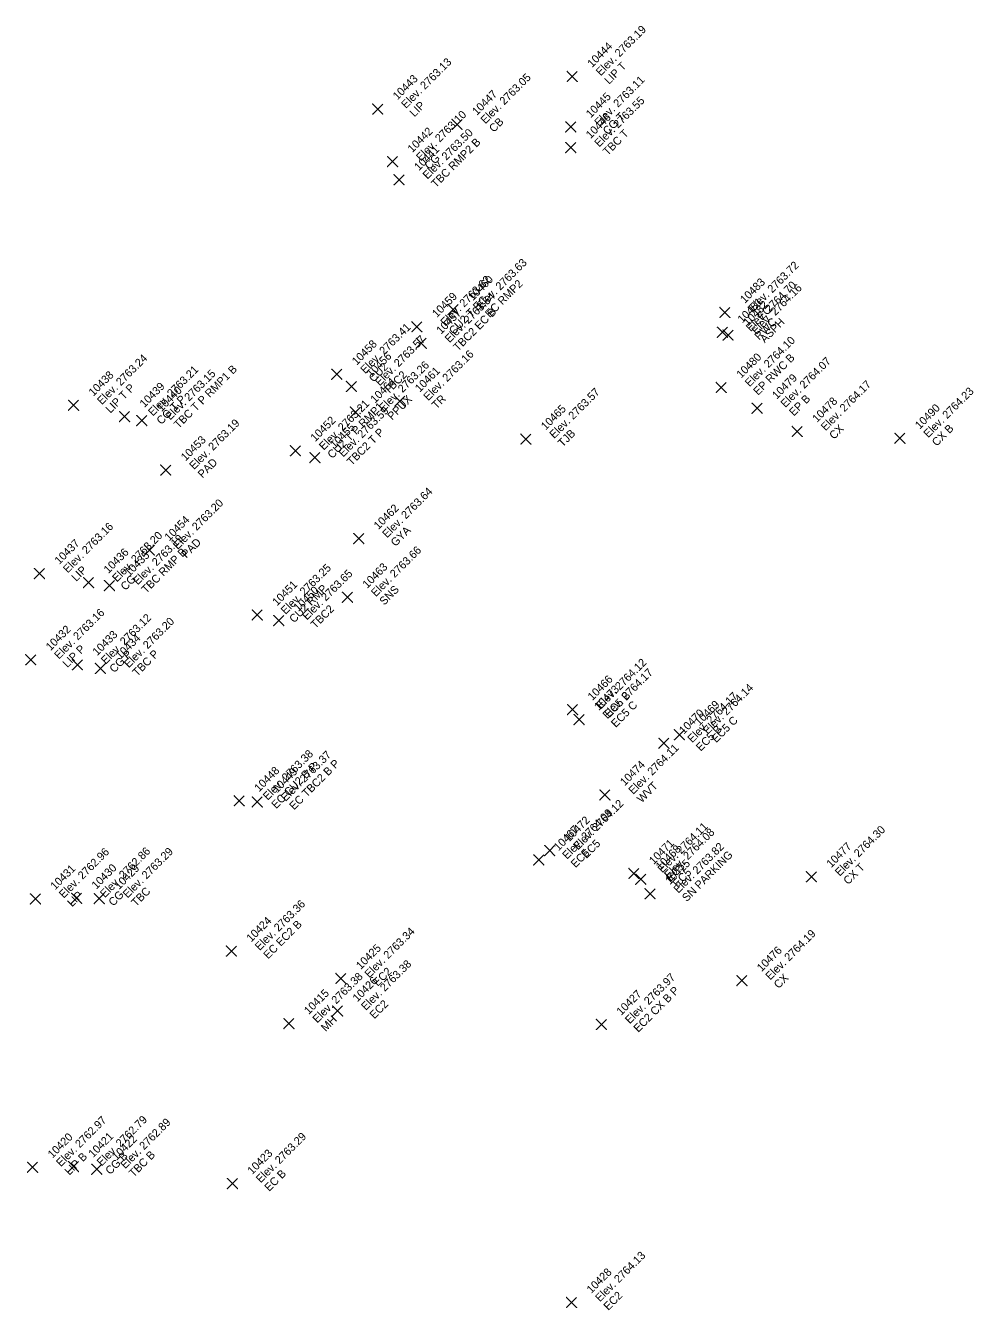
# Model space of a CAD drawing. Extents: x 2493999 to 2503109, y 700767 to 706646.
# Drawn here: x 2502616.97 to 2502645.41, y 701277.07 to 701315.61 of the extents above; entities that cross this region are included whole.
import ezdxf

# ---------------------------------------------------------------- set-up
doc = ezdxf.new("R2010")
doc.units = 0
doc.layers.add('ALG_CL_BLUE_Horiz', color=7, linetype='Continuous')
doc.layers.add('DES_SURFACE_Existing-Ground', color=7, linetype='Continuous')

msp = doc.modelspace()

# ---------------------------------------------------------------- linework, layer by layer
at = {"layer": 'ALG_CL_BLUE_Horiz'}
for points in [[(2502633.377, 701314.084), (2502633.227, 701314.234), (2502633.377, 701314.084), (2502633.227, 701313.934), (2502633.377, 701314.084), (2502633.527, 701313.934), (2502633.377, 701314.084), (2502633.527, 701314.234)], [(2502627.537, 701313.107), (2502627.387, 701313.257), (2502627.537, 701313.107), (2502627.387, 701312.957), (2502627.537, 701313.107), (2502627.687, 701312.957), (2502627.537, 701313.107), (2502627.687, 701313.257)], [(2502629.919, 701312.645), (2502629.769, 701312.795), (2502629.919, 701312.645), (2502629.769, 701312.495), (2502629.919, 701312.645), (2502630.069, 701312.495), (2502629.919, 701312.645), (2502630.069, 701312.795)], [(2502633.333, 701312.571), (2502633.183, 701312.721), (2502633.333, 701312.571), (2502633.183, 701312.421), (2502633.333, 701312.571), (2502633.483, 701312.421), (2502633.333, 701312.571), (2502633.483, 701312.721)], [(2502633.332, 701311.949), (2502633.182, 701312.099), (2502633.332, 701311.949), (2502633.182, 701311.799), (2502633.332, 701311.949), (2502633.482, 701311.799), (2502633.332, 701311.949), (2502633.482, 701312.099)], [(2502627.983, 701311.528), (2502627.833, 701311.678), (2502627.983, 701311.528), (2502627.833, 701311.378), (2502627.983, 701311.528), (2502628.133, 701311.378), (2502627.983, 701311.528), (2502628.133, 701311.678)], [(2502628.181, 701310.986), (2502628.031, 701311.136), (2502628.181, 701310.986), (2502628.031, 701310.836), (2502628.181, 701310.986), (2502628.331, 701310.836), (2502628.181, 701310.986), (2502628.331, 701311.136)], [(2502629.799, 701307.088), (2502629.649, 701307.238), (2502629.799, 701307.088), (2502629.649, 701306.938), (2502629.799, 701307.088), (2502629.949, 701306.938), (2502629.799, 701307.088), (2502629.949, 701307.238)], [(2502637.959, 701307.006), (2502637.809, 701307.156), (2502637.959, 701307.006), (2502637.809, 701306.856), (2502637.959, 701307.006), (2502638.109, 701306.856), (2502637.959, 701307.006), (2502638.109, 701307.156)], [(2502628.716, 701306.578), (2502628.566, 701306.728), (2502628.716, 701306.578), (2502628.566, 701306.428), (2502628.716, 701306.578), (2502628.866, 701306.428), (2502628.716, 701306.578), (2502628.866, 701306.728)], [(2502628.842, 701306.08), (2502628.692, 701306.23), (2502628.842, 701306.08), (2502628.692, 701305.93), (2502628.842, 701306.08), (2502628.992, 701305.93), (2502628.842, 701306.08), (2502628.992, 701306.23)], [(2502637.884, 701306.412), (2502637.734, 701306.562), (2502637.884, 701306.412), (2502637.734, 701306.262), (2502637.884, 701306.412), (2502638.034, 701306.262), (2502637.884, 701306.412), (2502638.034, 701306.562)], [(2502638.051, 701306.328), (2502637.901, 701306.478), (2502638.051, 701306.328), (2502637.901, 701306.178), (2502638.051, 701306.328), (2502638.201, 701306.178), (2502638.051, 701306.328), (2502638.201, 701306.478)], [(2502626.311, 701305.151), (2502626.161, 701305.301), (2502626.311, 701305.151), (2502626.161, 701305.001), (2502626.311, 701305.151), (2502626.461, 701305.001), (2502626.311, 701305.151), (2502626.461, 701305.301)], [(2502626.75, 701304.784), (2502626.6, 701304.934), (2502626.75, 701304.784), (2502626.6, 701304.634), (2502626.75, 701304.784), (2502626.9, 701304.634), (2502626.75, 701304.784), (2502626.9, 701304.934)], [(2502637.849, 701304.757), (2502637.699, 701304.907), (2502637.849, 701304.757), (2502637.699, 701304.607), (2502637.849, 701304.757), (2502637.999, 701304.607), (2502637.849, 701304.757), (2502637.999, 701304.907)], [(2502618.41, 701304.22), (2502618.26, 701304.37), (2502618.41, 701304.22), (2502618.26, 701304.07), (2502618.41, 701304.22), (2502618.56, 701304.07), (2502618.41, 701304.22), (2502618.56, 701304.37)], [(2502628.203, 701304.343), (2502628.053, 701304.493), (2502628.203, 701304.343), (2502628.053, 701304.193), (2502628.203, 701304.343), (2502628.353, 701304.193), (2502628.203, 701304.343), (2502628.353, 701304.493)], [(2502619.941, 701303.879), (2502619.791, 701304.029), (2502619.941, 701303.879), (2502619.791, 701303.729), (2502619.941, 701303.879), (2502620.091, 701303.729), (2502619.941, 701303.879), (2502620.091, 701304.029)], [(2502626.867, 701304.014), (2502626.717, 701304.164), (2502626.867, 701304.014), (2502626.717, 701303.864), (2502626.867, 701304.014), (2502627.017, 701303.864), (2502626.867, 701304.014), (2502627.017, 701304.164)], [(2502638.921, 701304.133), (2502638.771, 701304.283), (2502638.921, 701304.133), (2502638.771, 701303.983), (2502638.921, 701304.133), (2502639.071, 701303.983), (2502638.921, 701304.133), (2502639.071, 701304.283)], [(2502620.459, 701303.76), (2502620.309, 701303.91), (2502620.459, 701303.76), (2502620.309, 701303.61), (2502620.459, 701303.76), (2502620.609, 701303.61), (2502620.459, 701303.76), (2502620.609, 701303.91)], [(2502640.128, 701303.435), (2502639.978, 701303.585), (2502640.128, 701303.435), (2502639.978, 701303.285), (2502640.128, 701303.435), (2502640.278, 701303.285), (2502640.128, 701303.435), (2502640.278, 701303.585)], [(2502631.985, 701303.205), (2502631.835, 701303.355), (2502631.985, 701303.205), (2502631.835, 701303.055), (2502631.985, 701303.205), (2502632.135, 701303.055), (2502631.985, 701303.205), (2502632.135, 701303.355)], [(2502643.208, 701303.23), (2502643.058, 701303.38), (2502643.208, 701303.23), (2502643.058, 701303.08), (2502643.208, 701303.23), (2502643.358, 701303.08), (2502643.208, 701303.23), (2502643.358, 701303.38)], [(2502625.069, 701302.858), (2502624.919, 701303.008), (2502625.069, 701302.858), (2502624.919, 701302.708), (2502625.069, 701302.858), (2502625.219, 701302.708), (2502625.069, 701302.858), (2502625.219, 701303.008)], [(2502625.653, 701302.65), (2502625.503, 701302.8), (2502625.653, 701302.65), (2502625.503, 701302.5), (2502625.653, 701302.65), (2502625.803, 701302.5), (2502625.653, 701302.65), (2502625.803, 701302.8)], [(2502621.179, 701302.275), (2502621.029, 701302.425), (2502621.179, 701302.275), (2502621.029, 701302.125), (2502621.179, 701302.275), (2502621.329, 701302.125), (2502621.179, 701302.275), (2502621.329, 701302.425)], [(2502626.967, 701300.223), (2502626.817, 701300.373), (2502626.967, 701300.223), (2502626.817, 701300.073), (2502626.967, 701300.223), (2502627.117, 701300.073), (2502626.967, 701300.223), (2502627.117, 701300.373)], [(2502620.689, 701299.877), (2502620.539, 701300.027), (2502620.689, 701299.877), (2502620.539, 701299.727), (2502620.689, 701299.877), (2502620.839, 701299.727), (2502620.689, 701299.877), (2502620.839, 701300.027)], [(2502617.388, 701299.172), (2502617.238, 701299.322), (2502617.388, 701299.172), (2502617.238, 701299.022), (2502617.388, 701299.172), (2502617.538, 701299.022), (2502617.388, 701299.172), (2502617.538, 701299.322)], [(2502618.862, 701298.903), (2502618.712, 701299.053), (2502618.862, 701298.903), (2502618.712, 701298.753), (2502618.862, 701298.903), (2502619.012, 701298.753), (2502618.862, 701298.903), (2502619.012, 701299.053)], [(2502619.487, 701298.813), (2502619.337, 701298.963), (2502619.487, 701298.813), (2502619.337, 701298.663), (2502619.487, 701298.813), (2502619.637, 701298.663), (2502619.487, 701298.813), (2502619.637, 701298.963)], [(2502626.63, 701298.461), (2502626.48, 701298.611), (2502626.63, 701298.461), (2502626.48, 701298.311), (2502626.63, 701298.461), (2502626.78, 701298.311), (2502626.63, 701298.461), (2502626.78, 701298.611)], [(2502623.923, 701297.931), (2502623.773, 701298.081), (2502623.923, 701297.931), (2502623.773, 701297.781), (2502623.923, 701297.931), (2502624.073, 701297.781), (2502623.923, 701297.931), (2502624.073, 701298.081)], [(2502624.566, 701297.761), (2502624.416, 701297.911), (2502624.566, 701297.761), (2502624.416, 701297.611), (2502624.566, 701297.761), (2502624.716, 701297.611), (2502624.566, 701297.761), (2502624.716, 701297.911)], [(2502617.124, 701296.588), (2502616.974, 701296.738), (2502617.124, 701296.588), (2502616.974, 701296.438), (2502617.124, 701296.588), (2502617.274, 701296.438), (2502617.124, 701296.588), (2502617.274, 701296.738)], [(2502618.527, 701296.434), (2502618.377, 701296.584), (2502618.527, 701296.434), (2502618.377, 701296.284), (2502618.527, 701296.434), (2502618.677, 701296.284), (2502618.527, 701296.434), (2502618.677, 701296.584)], [(2502619.218, 701296.327), (2502619.068, 701296.477), (2502619.218, 701296.327), (2502619.068, 701296.177), (2502619.218, 701296.327), (2502619.368, 701296.177), (2502619.218, 701296.327), (2502619.368, 701296.477)], [(2502633.386, 701295.093), (2502633.236, 701295.243), (2502633.386, 701295.093), (2502633.236, 701294.943), (2502633.386, 701295.093), (2502633.536, 701294.943), (2502633.386, 701295.093), (2502633.536, 701295.243)], [(2502633.579, 701294.793), (2502633.429, 701294.943), (2502633.579, 701294.793), (2502633.429, 701294.643), (2502633.579, 701294.793), (2502633.729, 701294.643), (2502633.579, 701294.793), (2502633.729, 701294.943)], [(2502636.594, 701294.335), (2502636.444, 701294.485), (2502636.594, 701294.335), (2502636.444, 701294.185), (2502636.594, 701294.335), (2502636.744, 701294.185), (2502636.594, 701294.335), (2502636.744, 701294.485)], [(2502636.128, 701294.079), (2502635.978, 701294.229), (2502636.128, 701294.079), (2502635.978, 701293.929), (2502636.128, 701294.079), (2502636.278, 701293.929), (2502636.128, 701294.079), (2502636.278, 701294.229)], [(2502623.385, 701292.355), (2502623.235, 701292.505), (2502623.385, 701292.355), (2502623.235, 701292.205), (2502623.385, 701292.355), (2502623.535, 701292.205), (2502623.385, 701292.355), (2502623.535, 701292.505)], [(2502623.925, 701292.32), (2502623.775, 701292.47), (2502623.925, 701292.32), (2502623.775, 701292.17), (2502623.925, 701292.32), (2502624.075, 701292.17), (2502623.925, 701292.32), (2502624.075, 701292.47)], [(2502634.357, 701292.531), (2502634.207, 701292.681), (2502634.357, 701292.531), (2502634.207, 701292.381), (2502634.357, 701292.531), (2502634.507, 701292.381), (2502634.357, 701292.531), (2502634.507, 701292.681)], [(2502632.698, 701290.863), (2502632.548, 701291.013), (2502632.698, 701290.863), (2502632.548, 701290.713), (2502632.698, 701290.863), (2502632.848, 701290.713), (2502632.698, 701290.863), (2502632.848, 701291.013)], [(2502632.37, 701290.583), (2502632.22, 701290.733), (2502632.37, 701290.583), (2502632.22, 701290.433), (2502632.37, 701290.583), (2502632.52, 701290.433), (2502632.37, 701290.583), (2502632.52, 701290.733)], [(2502635.228, 701290.175), (2502635.078, 701290.325), (2502635.228, 701290.175), (2502635.078, 701290.025), (2502635.228, 701290.175), (2502635.378, 701290.025), (2502635.228, 701290.175), (2502635.378, 701290.325)], [(2502635.43, 701290), (2502635.28, 701290.15), (2502635.43, 701290), (2502635.28, 701289.85), (2502635.43, 701290), (2502635.58, 701289.85), (2502635.43, 701290), (2502635.58, 701290.15)], [(2502640.552, 701290.078), (2502640.402, 701290.228), (2502640.552, 701290.078), (2502640.402, 701289.928), (2502640.552, 701290.078), (2502640.702, 701289.928), (2502640.552, 701290.078), (2502640.702, 701290.228)], [(2502635.71, 701289.568), (2502635.56, 701289.718), (2502635.71, 701289.568), (2502635.56, 701289.418), (2502635.71, 701289.568), (2502635.86, 701289.418), (2502635.71, 701289.568), (2502635.86, 701289.718)], [(2502617.265, 701289.412), (2502617.115, 701289.562), (2502617.265, 701289.412), (2502617.115, 701289.262), (2502617.265, 701289.412), (2502617.415, 701289.262), (2502617.265, 701289.412), (2502617.415, 701289.562)], [(2502618.499, 701289.433), (2502618.349, 701289.583), (2502618.499, 701289.433), (2502618.349, 701289.283), (2502618.499, 701289.433), (2502618.649, 701289.283), (2502618.499, 701289.433), (2502618.649, 701289.583)], [(2502619.182, 701289.422), (2502619.032, 701289.572), (2502619.182, 701289.422), (2502619.032, 701289.272), (2502619.182, 701289.422), (2502619.332, 701289.272), (2502619.182, 701289.422), (2502619.332, 701289.572)], [(2502623.147, 701287.849), (2502622.997, 701287.999), (2502623.147, 701287.849), (2502622.997, 701287.699), (2502623.147, 701287.849), (2502623.297, 701287.699), (2502623.147, 701287.849), (2502623.297, 701287.999)], [(2502626.435, 701287.027), (2502626.285, 701287.177), (2502626.435, 701287.027), (2502626.285, 701286.877), (2502626.435, 701287.027), (2502626.585, 701286.877), (2502626.435, 701287.027), (2502626.585, 701287.177)], [(2502638.465, 701286.96), (2502638.315, 701287.11), (2502638.465, 701286.96), (2502638.315, 701286.81), (2502638.465, 701286.96), (2502638.615, 701286.81), (2502638.465, 701286.96), (2502638.615, 701287.11)], [(2502626.333, 701286.05), (2502626.183, 701286.2), (2502626.333, 701286.05), (2502626.183, 701285.9), (2502626.333, 701286.05), (2502626.483, 701285.9), (2502626.333, 701286.05), (2502626.483, 701286.2)], [(2502624.875, 701285.674), (2502624.725, 701285.824), (2502624.875, 701285.674), (2502624.725, 701285.524), (2502624.875, 701285.674), (2502625.025, 701285.524), (2502624.875, 701285.674), (2502625.025, 701285.824)], [(2502634.252, 701285.649), (2502634.102, 701285.799), (2502634.252, 701285.649), (2502634.102, 701285.499), (2502634.252, 701285.649), (2502634.402, 701285.499), (2502634.252, 701285.649), (2502634.402, 701285.799)], [(2502617.183, 701281.361), (2502617.033, 701281.511), (2502617.183, 701281.361), (2502617.033, 701281.211), (2502617.183, 701281.361), (2502617.333, 701281.211), (2502617.183, 701281.361), (2502617.333, 701281.511)], [(2502618.404, 701281.38), (2502618.254, 701281.53), (2502618.404, 701281.38), (2502618.254, 701281.23), (2502618.404, 701281.38), (2502618.554, 701281.23), (2502618.404, 701281.38), (2502618.554, 701281.53)], [(2502619.109, 701281.301), (2502618.959, 701281.451), (2502619.109, 701281.301), (2502618.959, 701281.151), (2502619.109, 701281.301), (2502619.259, 701281.151), (2502619.109, 701281.301), (2502619.259, 701281.451)], [(2502623.178, 701280.874), (2502623.028, 701281.024), (2502623.178, 701280.874), (2502623.028, 701280.724), (2502623.178, 701280.874), (2502623.328, 701280.724), (2502623.178, 701280.874), (2502623.328, 701281.024)], [(2502633.356, 701277.307), (2502633.206, 701277.457), (2502633.356, 701277.307), (2502633.206, 701277.157), (2502633.356, 701277.307), (2502633.506, 701277.157), (2502633.356, 701277.307), (2502633.506, 701277.457)]]:
    msp.add_lwpolyline(points, dxfattribs=at)

# ---------------------------------------------------------------- texts
at = {"layer": 'DES_SURFACE_Existing-Ground'}
for s, p in [('Elev. 2763.19', (2502634.226, 701314.084)), ('10444', (2502633.971, 701314.339)), ('Elev. 2763.13', (2502628.386, 701313.107)), ('LIP T', (2502634.48, 701313.829)), ('10443', (2502628.131, 701313.362)), ('Elev. 2763.05', (2502630.768, 701312.645)), ('Elev. 2763.11', (2502634.182, 701312.571)), ('10447', (2502630.513, 701312.9)), ('10445', (2502633.927, 701312.826)), ('LIP', (2502628.64, 701312.852)), ('Elev. 2763.55', (2502634.181, 701311.949)), ('Elev. 2763.10', (2502628.832, 701311.528)), ('CB', (2502631.022, 701312.39)), ('10446', (2502633.926, 701312.204)), ('CG T', (2502634.436, 701312.316)), ('10442', (2502628.577, 701311.783)), ('Elev. 2763.50', (2502629.03, 701310.986)), ('TBC T', (2502634.435, 701311.694)), ('TBC RMP2 B', (2502629.284, 701310.731)), ('10441', (2502628.775, 701311.241)), ('CG', (2502629.086, 701311.273)), ('Elev. 2763.63', (2502630.648, 701307.088)), ('Elev. 2763.72', (2502638.808, 701307.006)), ('Elev. 2763.62', (2502629.565, 701306.578)), ('10460', (2502630.393, 701307.343)), ('EC RMP2', (2502630.902, 701306.833)), ('10483', (2502638.553, 701307.261)), ('Elev. 2764.70', (2502638.733, 701306.412)), ('Elev. 2764.16', (2502638.9, 701306.328)), ('10459', (2502629.31, 701306.833)), ('Elev. 2763.54', (2502629.691, 701306.08)), ('CU2 T EC', (2502629.819, 701306.323)), ('10481', (2502638.478, 701306.667)), ('10457', (2502629.436, 701306.335)), ('TBC2 EC B', (2502629.945, 701305.825)), ('10482', (2502638.645, 701306.583)), ('EC', (2502639.062, 701306.751)), ('Elev. 2763.41', (2502627.16, 701305.151)), ('RWC', (2502638.987, 701306.157)), ('ASPH', (2502639.154, 701306.073)), ('Elev. 2763.57', (2502627.599, 701304.784)), ('Elev. 2764.10', (2502638.698, 701304.757)), ('10458', (2502626.905, 701305.406)), ('Elev. 2763.16', (2502629.052, 701304.343)), ('Elev. 2763.24', (2502619.259, 701304.22)), ('10456', (2502627.344, 701305.039)), ('CU2', (2502627.414, 701304.896)), ('Elev. 2763.26', (2502627.716, 701304.014)), ('10480', (2502638.443, 701305.012)), ('EP RWC B', (2502638.952, 701304.502)), ('Elev. 2764.07', (2502639.77, 701304.133)), ('10438', (2502619.004, 701304.475)), ('Elev. 2763.21', (2502620.79, 701303.879)), ('Elev. 2763.15', (2502621.308, 701303.76)), ('TBC T P RMP1 B', (2502621.562, 701303.505)), ('TBC2', (2502627.853, 701304.529)), ('10461', (2502628.797, 701304.598)), ('10479', (2502639.515, 701304.388)), ('LIP T P', (2502619.513, 701303.965)), ('10439', (2502620.535, 701304.134)), ('10440', (2502621.053, 701304.015)), ('10464', (2502627.461, 701304.269)), ('Elev. 2763.57', (2502632.834, 701303.205)), ('Elev. 2764.17', (2502640.977, 701303.435)), ('Elev. 2764.23', (2502644.057, 701303.23)), ('CG T P', (2502621.044, 701303.624)), ('Elev. 2763.21', (2502625.918, 701302.858)), ('PPUX', (2502627.97, 701303.759)), ('TR', (2502629.306, 701304.088)), ('EP B', (2502640.024, 701303.878)), ('10478', (2502640.722, 701303.69)), ('CU2 T P RMP1', (2502626.172, 701302.603)), ('Elev. 2763.59', (2502626.502, 701302.65)), ('10465', (2502632.579, 701303.46)), ('10490', (2502643.802, 701303.485)), ('Elev. 2763.19', (2502622.028, 701302.275)), ('10452', (2502625.663, 701303.113)), ('10455', (2502626.247, 701302.905)), ('CX', (2502641.231, 701303.18)), ('CX B', (2502644.311, 701302.975)), ('10453', (2502621.773, 701302.53)), ('TBC2 T P', (2502626.756, 701302.395)), ('TJB', (2502633.088, 701302.95)), ('PAD', (2502622.282, 701302.02)), ('Elev. 2763.64', (2502627.816, 701300.223)), ('Elev. 2763.20', (2502621.538, 701299.877)), ('10462', (2502627.561, 701300.478)), ('10454', (2502621.283, 701300.132)), ('Elev. 2763.16', (2502618.237, 701299.172)), ('GYA', (2502628.07, 701299.968)), ('10437', (2502617.982, 701299.427)), ('Elev. 2763.20', (2502619.711, 701298.903)), ('Elev. 2763.19', (2502620.336, 701298.813)), ('PAD', (2502621.792, 701299.622)), ('10436', (2502619.456, 701299.158)), ('10435', (2502620.081, 701299.068)), ('TBC RMP B', (2502620.59, 701298.558)), ('Elev. 2763.66', (2502627.479, 701298.461)), ('LIP', (2502618.491, 701298.917)), ('Elev. 2763.25', (2502624.772, 701297.931)), ('Elev. 2763.65', (2502625.415, 701297.761)), ('10463', (2502627.224, 701298.716)), ('CG', (2502619.965, 701298.648)), ('10451', (2502624.517, 701298.186)), ('CU2 RMP', (2502625.026, 701297.676)), ('10450', (2502625.16, 701298.016)), ('SNS', (2502627.733, 701298.206)), ('TBC2', (2502625.669, 701297.506)), ('Elev. 2763.16', (2502617.973, 701296.588)), ('Elev. 2763.12', (2502619.376, 701296.434)), ('Elev. 2763.20', (2502620.067, 701296.327)), ('10432', (2502617.718, 701296.843)), ('10433', (2502619.121, 701296.689)), ('LIP P', (2502618.227, 701296.333)), ('10434', (2502619.812, 701296.582)), ('CG P', (2502619.63, 701296.179)), ('TBC P', (2502620.321, 701296.072)), ('Elev. 2764.12', (2502634.235, 701295.093)), ('Elev. 2764.17', (2502634.428, 701294.793)), ('10466', (2502633.98, 701295.348)), ('Elev. 2764.14', (2502637.443, 701294.335)), ('10473', (2502634.173, 701295.048)), ('EC5 B', (2502634.489, 701294.838)), ('Elev. 2764.17', (2502636.977, 701294.079)), ('EC5 C', (2502634.682, 701294.538)), ('10470', (2502636.722, 701294.334)), ('10469', (2502637.188, 701294.59)), ('EC5 C', (2502637.697, 701294.08)), ('EC5 B', (2502637.231, 701293.824)), ('Elev. 2764.11', (2502635.206, 701292.531)), ('Elev. 2763.38', (2502624.234, 701292.355)), ('Elev. 2763.37', (2502624.774, 701292.32)), ('EC TBC2 B P', (2502625.028, 701292.065)), ('10474', (2502634.951, 701292.786)), ('10448', (2502623.979, 701292.61)), ('EC CU2 B P', (2502624.488, 701292.1)), ('10449', (2502624.519, 701292.575)), ('WVT', (2502635.46, 701292.276)), ('Elev. 2764.12', (2502633.547, 701290.863)), ('Elev. 2764.09', (2502633.219, 701290.583)), ('10467', (2502632.964, 701290.838)), ('10472', (2502633.292, 701291.118)), ('Elev. 2764.11', (2502636.077, 701290.175)), ('Elev. 2764.30', (2502641.401, 701290.078)), ('EC5', (2502633.801, 701290.608)), ('Elev. 2764.08', (2502636.279, 701290)), ('Elev. 2762.96', (2502618.114, 701289.412)), ('Elev. 2762.86', (2502619.348, 701289.433)), ('Elev. 2763.29', (2502620.031, 701289.422)), ('EC5', (2502633.473, 701290.328)), ('10471', (2502635.822, 701290.43)), ('10468', (2502636.024, 701290.255)), ('Elev. 2763.82', (2502636.559, 701289.568)), ('SN PARKING', (2502636.813, 701289.313)), ('10477', (2502641.146, 701290.333)), ('10430', (2502619.093, 701289.688)), ('10429', (2502619.776, 701289.677)), ('EC5', (2502636.331, 701289.92)), ('10475', (2502636.304, 701289.823)), ('CX T', (2502641.655, 701289.823)), ('10431', (2502617.859, 701289.667)), ('EC5', (2502636.533, 701289.745)), ('TBC', (2502620.285, 701289.167)), ('LIP', (2502618.368, 701289.157)), ('CG', (2502619.602, 701289.178)), ('Elev. 2763.36', (2502623.996, 701287.849)), ('10424', (2502623.741, 701288.104)), ('EC EC2 B', (2502624.25, 701287.594)), ('Elev. 2763.34', (2502627.284, 701287.027)), ('Elev. 2764.19', (2502639.314, 701286.96)), ('10425', (2502627.029, 701287.282)), ('10476', (2502639.059, 701287.215)), ('Elev. 2763.38', (2502627.182, 701286.05)), ('EC2', (2502627.538, 701286.772)), ('Elev. 2763.38', (2502625.724, 701285.674)), ('10426', (2502626.927, 701286.305)), ('Elev. 2763.97', (2502635.101, 701285.649)), ('CX', (2502639.568, 701286.705)), ('10415', (2502625.469, 701285.929)), ('10427', (2502634.846, 701285.904)), ('EC2 CX B P', (2502635.355, 701285.394)), ('EC2', (2502627.436, 701285.795)), ('MH', (2502625.978, 701285.419)), ('Elev. 2762.97', (2502618.032, 701281.361)), ('Elev. 2762.79', (2502619.253, 701281.38)), ('Elev. 2762.89', (2502619.958, 701281.301)), ('10420', (2502617.777, 701281.616)), ('10421', (2502618.998, 701281.635)), ('Elev. 2763.29', (2502624.027, 701280.874)), ('10422', (2502619.703, 701281.556)), ('LIP B', (2502618.286, 701281.106)), ('CG B', (2502619.507, 701281.125)), ('TBC B', (2502620.212, 701281.046)), ('10423', (2502623.772, 701281.129)), ('EC B', (2502624.281, 701280.619)), ('Elev. 2764.13', (2502634.205, 701277.307)), ('10428', (2502633.95, 701277.562)), ('EC2', (2502634.459, 701277.052))]:
    msp.add_text(s, height=0.24, rotation=45, dxfattribs=at).set_placement(p)

doc.saveas('drawing.dxf')
